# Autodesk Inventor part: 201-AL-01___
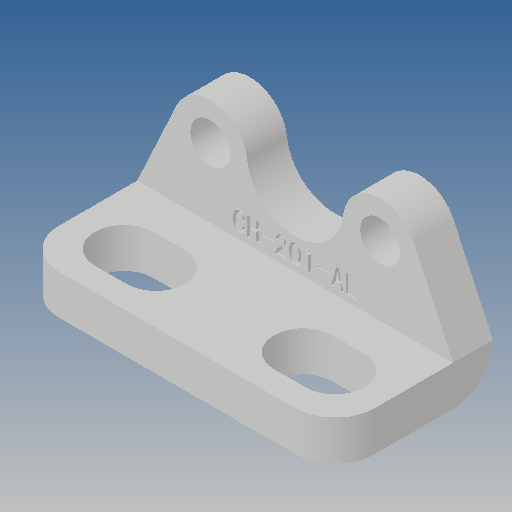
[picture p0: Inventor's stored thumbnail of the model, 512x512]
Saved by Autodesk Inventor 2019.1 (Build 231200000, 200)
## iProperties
Created: 2010-06
Part Number: 201-AL-01___
Material: Ogólny
Document SubType Name: Modeling
Designer: CADENGINEERING4
Density: 1 g/cm^3
Appearance: Domyślna
Author: CADENGINEERING4
Revision Number: ANY
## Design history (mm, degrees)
feature "NONE"
node "Bryła1"
